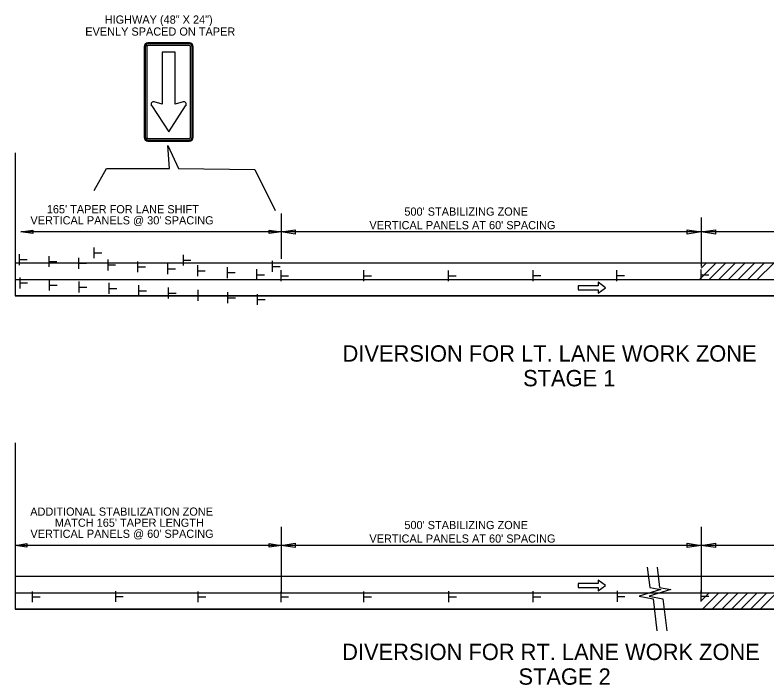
# Model space of a CAD drawing. Extents: x 1930579 to 1937521, y 596183 to 597599.
# Drawn here: x 1935116 to 1935668, y 596397 to 596889 of the extents above; entities that cross this region are included whole.
import ezdxf

# ---------------------------------------------------------------- set-up
doc = ezdxf.new("R2010")
doc.units = 0
for name, color, linetype in [('Default', 7, 'Continuous'), ('P_TC_Signs_Permanent', 7, 'Continuous'), ('R_Annotation', 7, 'Continuous'), ('R_Striping', 7, 'Continuous')]:
    doc.layers.add(name, color=color, linetype=linetype)

msp = doc.modelspace()

# ---------------------------------------------------------------- linework, layer by layer
at = {"layer": 'Default'}
for p, q in [((1935116.21, 596787.58), (1935116.21, 596682.66)), ((1935311.54, 596743.12), (1935311.54, 596709.71)), ((1935620.14, 596740.12), (1935620.14, 596704.24)), ((1935120.48, 596729.59), (1935129.18, 596730.89)), ((1935311.54, 596729.59), (1935120.48, 596729.59)), ((1935129.18, 596728.29), (1935120.48, 596729.59)), ((1935129.18, 596730.89), (1935129.18, 596728.29)), ((1935302.85, 596728.29), (1935302.85, 596730.89)), ((1935302.85, 596730.89), (1935311.54, 596729.59)), ((1935311.54, 596729.59), (1935302.85, 596728.29)), ((1935620.14, 596729.59), (1935311.54, 596729.59)), ((1935311.62, 596729.59), (1935321.93, 596731.14)), ((1935321.93, 596728.04), (1935311.62, 596729.59)), ((1935321.93, 596731.14), (1935321.93, 596728.04)), ((1935609.84, 596728.04), (1935609.84, 596731.14)), ((1935609.84, 596731.14), (1935620.14, 596729.59)), ((1935620.14, 596729.59), (1935609.84, 596728.04)), ((1935620.14, 596729.59), (1935630.45, 596731.14)), ((1935955.49, 596729.59), (1935620.14, 596729.59)), ((1935630.45, 596728.04), (1935620.14, 596729.59)), ((1935630.45, 596731.14), (1935630.45, 596728.04)), ((1935174.4, 596710.23), (1935174.4, 596718.21)), ((1935119.53, 596705.25), (1935119.53, 596713.23)), ((1935174.52, 596714.19), (1935179.97, 596714.19)), ((1935239.82, 596704.81), (1935239.82, 596712.79)), ((1935119.65, 596709.22), (1935125.09, 596709.22)), ((1935141.27, 596703.9), (1935141.27, 596711.88)), ((1935141.39, 596707.87), (1935146.84, 596707.87)), ((1935163.02, 596702.55), (1935163.02, 596710.53)), ((1935184.51, 596701.36), (1935184.51, 596709.34)), ((1935206.46, 596699.95), (1935206.46, 596707.93)), ((1935239.93, 596708.78), (1935245.38, 596708.78)), ((1935305.38, 596700.3), (1935305.38, 596708.28)), ((1936166.23, 596706.66), (1935116.21, 596706.66)), ((1935163.13, 596706.52), (1935168.58, 596706.52)), ((1935184.62, 596705.33), (1935190.07, 596705.33)), ((1935206.58, 596703.92), (1935212.02, 596703.92)), ((1935228.41, 596698.53), (1935228.41, 596706.51)), ((1935228.53, 596702.5), (1935233.97, 596702.5)), ((1935250.36, 596697.12), (1935250.36, 596705.1)), ((1935272.31, 596695.7), (1935272.31, 596703.68)), ((1935293.81, 596694.23), (1935293.81, 596702.21)), ((1935305.5, 596704.27), (1935310.94, 596704.27)), ((1935311.54, 596693.46), (1935311.54, 596701.44)), ((1935372.39, 596693.46), (1935372.39, 596701.44)), ((1935434.53, 596693.31), (1935434.53, 596701.29)), ((1935496.67, 596693.52), (1935496.67, 596701.5)), ((1935558.15, 596693.54), (1935558.15, 596701.52)), ((1935618.84, 596694.66), (1935630.84, 596706.66)), ((1935620.14, 596703.04), (1935623.77, 596706.66)), ((1935620.14, 596694.12), (1935620.14, 596702.1)), ((1935625.91, 596694.66), (1935637.91, 596706.66)), ((1935632.98, 596694.66), (1935644.98, 596706.66)), ((1935640.05, 596694.66), (1935652.05, 596706.66)), ((1935647.12, 596694.66), (1935659.12, 596706.66)), ((1935654.19, 596694.66), (1935666.19, 596706.66)), ((1935661.26, 596694.66), (1935673.26, 596706.66)), ((1935119.9, 596688.15), (1935119.9, 596696.13)), ((1935250.48, 596701.09), (1935255.93, 596701.09)), ((1935272.43, 596699.67), (1935277.88, 596699.67)), ((1935293.93, 596698.19), (1935299.38, 596698.19)), ((1935311.66, 596697.43), (1935317.1, 596697.43)), ((1935372.51, 596697.43), (1935377.96, 596697.43)), ((1935434.65, 596697.28), (1935440.1, 596697.28)), ((1935496.79, 596697.49), (1935502.23, 596697.49)), ((1935558.27, 596697.5), (1935563.72, 596697.5)), ((1935620.26, 596698.09), (1935625.71, 596698.09)), ((1935116.21, 596694.66), (1936166.23, 596694.66)), ((1935120.01, 596692.11), (1935125.46, 596692.11)), ((1935141.62, 596686.64), (1935141.62, 596694.62)), ((1935141.74, 596690.6), (1935147.19, 596690.6)), ((1935163.34, 596685.13), (1935163.34, 596693.11)), ((1935185.37, 596684.19), (1935185.37, 596692.17)), ((1935207.17, 596682.47), (1935207.17, 596690.45)), ((1935163.46, 596689.09), (1935168.91, 596689.09)), ((1935185.49, 596688.15), (1935190.94, 596688.15)), ((1935207.28, 596686.44), (1935212.73, 596686.44)), ((1935228.96, 596680.75), (1935228.96, 596688.73)), ((1935229.07, 596684.72), (1935234.52, 596684.72)), ((1935250.75, 596679.03), (1935250.75, 596687.01)), ((1935272.54, 596677.31), (1935272.54, 596685.29)), ((1935116.21, 596682.66), (1935396.72, 596682.66)), ((1936166.23, 596682.66), (1935116.21, 596682.66)), ((1935250.87, 596683), (1935256.31, 596683)), ((1935272.66, 596681.28), (1935278.1, 596681.28)), ((1935294.33, 596676), (1935294.33, 596683.98)), ((1935294.45, 596679.97), (1935299.9, 596679.97)), ((1935380.85, 596682.66), (1935655.91, 596682.66)), ((1935593.17, 596682.66), (1935619.93, 596682.66)), ((1935619.93, 596682.66), (1935770.53, 596682.66)), ((1935116.21, 596574.86), (1935116.21, 596452.57)), ((1935311.54, 596513.03), (1935311.54, 596464.57)), ((1935620.14, 596513.03), (1935620.14, 596474.15)), ((1935620.14, 596513.03), (1935620.14, 596464.57)), ((1935116.21, 596499.5), (1935124.9, 596500.8)), ((1935311.54, 596499.5), (1935116.21, 596499.5)), ((1935124.9, 596498.19), (1935116.21, 596499.5)), ((1935124.9, 596500.8), (1935124.9, 596498.19)), ((1935302.85, 596498.19), (1935302.85, 596500.8)), ((1935302.85, 596500.8), (1935311.54, 596499.5)), ((1935311.54, 596499.5), (1935302.85, 596498.19)), ((1935620.14, 596499.5), (1935311.54, 596499.5)), ((1935311.62, 596499.5), (1935321.93, 596501.04)), ((1935321.93, 596497.95), (1935311.62, 596499.5)), ((1935321.93, 596501.04), (1935321.93, 596497.95)), ((1935609.84, 596497.95), (1935609.84, 596501.04)), ((1935609.84, 596501.04), (1935620.14, 596499.5)), ((1935620.14, 596499.5), (1935609.84, 596497.95)), ((1935620.14, 596499.5), (1935630.45, 596501.04)), ((1935955.49, 596499.5), (1935620.14, 596499.5)), ((1935630.45, 596497.95), (1935620.14, 596499.5)), ((1935630.45, 596501.04), (1935630.45, 596497.95)), ((1936166.23, 596476.57), (1935116.21, 596476.57)), ((1935116.21, 596464.57), (1936166.23, 596464.57)), ((1935128.97, 596457.74), (1935128.97, 596465.72)), ((1935190.14, 596457.93), (1935190.14, 596465.91)), ((1935250.68, 596457.74), (1935250.68, 596465.72)), ((1935311.54, 596457.74), (1935311.54, 596465.72)), ((1935372.39, 596457.74), (1935372.39, 596465.72)), ((1935434.85, 596457.79), (1935434.85, 596465.77)), ((1935496.67, 596457.8), (1935496.67, 596465.78)), ((1935558.47, 596458.01), (1935558.47, 596465.99)), ((1935620.14, 596458.29), (1935620.14, 596466.27)), ((1935620.14, 596458.8), (1935625.91, 596464.57)), ((1935620.98, 596452.57), (1935632.98, 596464.57)), ((1935628.05, 596452.57), (1935640.05, 596464.57)), ((1935635.12, 596452.57), (1935647.12, 596464.57)), ((1935642.19, 596452.57), (1935654.19, 596464.57)), ((1935649.26, 596452.57), (1935661.26, 596464.57)), ((1935656.34, 596452.57), (1935668.34, 596464.57)), ((1935663.41, 596452.57), (1935675.41, 596464.57)), ((1935129.09, 596461.71), (1935134.54, 596461.71)), ((1935190.26, 596461.9), (1935195.71, 596461.9)), ((1935250.8, 596461.71), (1935256.25, 596461.71)), ((1935311.66, 596461.71), (1935317.1, 596461.71)), ((1935372.51, 596461.71), (1935377.96, 596461.71)), ((1935434.97, 596461.76), (1935440.42, 596461.76)), ((1935496.79, 596461.77), (1935502.23, 596461.77)), ((1935558.59, 596461.98), (1935564.04, 596461.98)), ((1935620.26, 596462.26), (1935625.71, 596462.26)), ((1935116.21, 596452.57), (1935396.72, 596452.57)), ((1936166.23, 596452.57), (1935116.21, 596452.57)), ((1935380.85, 596452.57), (1935655.91, 596452.57)), ((1935593.17, 596452.57), (1935619.93, 596452.57)), ((1935619.93, 596452.57), (1935770.53, 596452.57))]:
    msp.add_line(p, q, dxfattribs=at)
for points in [[(1935580.39, 596483.47), (1935582.26, 596468.46), (1935590.52, 596467), (1935574.49, 596462.14), (1935584.69, 596460.2), (1935587.51, 596436.81)], [(1935587.67, 596483.47), (1935589.55, 596468.46), (1935597.8, 596467), (1935581.78, 596462.14), (1935591.98, 596460.2), (1935594.79, 596436.81)]]:
    msp.add_lwpolyline(points, dxfattribs=at)
at = {"layer": 'P_TC_Signs_Permanent'}
for p, q in [((1935244.21, 596868.29), (1935213.83, 596868.29)), ((1935244.21, 596867.54), (1935213.83, 596867.54)), ((1935211.02, 596865.48), (1935211.02, 596799.11)), ((1935211.77, 596865.48), (1935211.77, 596799.11)), ((1935212.9, 596865.48), (1935212.9, 596799.11)), ((1935244.21, 596866.42), (1935213.83, 596866.42)), ((1935245.15, 596799.11), (1935245.15, 596865.48)), ((1935246.27, 596799.11), (1935246.27, 596865.48)), ((1935247.02, 596799.11), (1935247.02, 596865.48)), ((1935213.83, 596798.17), (1935244.21, 596798.17)), ((1935213.83, 596797.04), (1935244.21, 596797.04)), ((1935213.83, 596796.29), (1935244.21, 596796.29))]:
    msp.add_line(p, q, dxfattribs=at)
for points in [[(1935239.65, 596825), (1935233.9, 596823.28), (1935233.9, 596861.54), (1935224.15, 596861.54), (1935224.15, 596823.28), (1935218.4, 596825.03)], [(1935216.58, 596822.04), (1935229.02, 596803.04), (1935241.43, 596822.05)]]:
    msp.add_lwpolyline(points, dxfattribs=at)
for centre, radius, start, end in [((1935213.83, 596865.48), 2.81, 90, 180), ((1935213.83, 596865.48), 2.06, 90, 180), ((1935244.21, 596865.48), 2.81, 360, 90), ((1935244.21, 596865.48), 2.06, 360, 90), ((1935213.83, 596865.48), 0.938, 90, 180), ((1935244.21, 596865.48), 0.937, 360, 90), ((1935217.9, 596823.3), 1.8, 74.0309, 213.4755), ((1935240.14, 596823.3), 1.76, 326.5994, 105.9691), ((1935153.84, 596780.94), 75, 33.2286, 33.4755), ((1935304.23, 596781.04), 75, 146.5994, 146.857), ((1935213.83, 596799.11), 2.81, 180, 270), ((1935213.83, 596799.11), 2.06, 180, 270), ((1935213.83, 596799.11), 0.938, 180, 270), ((1935244.21, 596799.11), 2.81, 270, 360), ((1935244.21, 596799.11), 2.06, 270, 360), ((1935244.21, 596799.11), 0.938, 270, 360)]:
    msp.add_arc(centre, radius, start, end, dxfattribs=at)
at = {"layer": 'R_Annotation'}
msp.add_lwpolyline([(1935174.4, 596759.89), (1935183.41, 596776.2), (1935229.64, 596776.2), (1935228.44, 596793.08), (1935236.25, 596776.2), (1935292.26, 596775.38), (1935307.32, 596745.25)], dxfattribs=at)
at = {"layer": 'R_Striping'}
for points in [[(1935544.48, 596684.61), (1935549.67, 596688.61), (1935544.48, 596692.61), (1935544.48, 596690.11), (1935529.77, 596690.11), (1935529.77, 596687.11), (1935544.48, 596687.11)], [(1935544.48, 596466.04), (1935549.67, 596470.04), (1935544.48, 596474.04), (1935544.48, 596471.54), (1935529.77, 596471.54), (1935529.77, 596468.54), (1935544.48, 596468.54)]]:
    msp.add_lwpolyline(points, close=True, dxfattribs=at)

# ---------------------------------------------------------------- texts
at = {"layer": 'Default'}
for s, height, p in [("165' TAPER FOR LANE SHIFT", 6, (1935139.53, 596743.22)), ("500' STABILIZING ZONE", 5.9999, (1935402.09, 596741.5)), ("VERTICAL PANELS @ 30' SPACING", 6, (1935127.5, 596735.09)), ("VERTICAL PANELS AT 60' SPACING", 5.9999, (1935376.41, 596731.57)), ('DIVERSION FOR LT. LANE WORK ZONE', 12, (1935356.7, 596634.35)), ('STAGE 1', 12, (1935489.26, 596616.23)), ('ADDITIONAL STABILIZATION ZONE', 6, (1935127.37, 596521.25)), ("MATCH 165' TAPER LENGTH", 6, (1935145.41, 596513.12)), ("500' STABILIZING ZONE", 5.9999, (1935402.09, 596511.41)), ("VERTICAL PANELS @ 60' SPACING", 6, (1935127.5, 596505)), ("VERTICAL PANELS AT 60' SPACING", 5.9999, (1935376.41, 596501.48)), ('DIVERSION FOR RT. LANE WORK ZONE', 12, (1935356.41, 596415.3)), ('STAGE 2', 12, (1935485.86, 596397.18))]:
    msp.add_text(s, height=height, rotation=360, dxfattribs=at).set_placement(p)
at = {"layer": 'R_Annotation'}
for s, p in [('HIGHWAY (48" X 24")', (1935182.06, 596882.44)), ('EVENLY SPACED ON TAPER', (1935167.77, 596873.65))]:
    msp.add_text(s, height=6, rotation=0.0075, dxfattribs=at).set_placement(p)

doc.saveas('drawing.dxf')
